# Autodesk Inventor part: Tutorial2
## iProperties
Shininess: 64.0
Length Units: 11269
Angle Units: 11279
Time Units: 11290
Mass Units: 11283
Length Display Precision: 3
Angle Display Precision: 2
Compacted: True
Part Number: Tutorial2
Document SubType Name: Modeling
Created: 2002-11
Designer: deepak
Density: 1 g/cm^3
Density: 0.0
Volumn: 0.0
Area: 0.0
PropertySet Name: Model Information
Control State: 0
Master: False
Checked Out: False
Author: deepak
